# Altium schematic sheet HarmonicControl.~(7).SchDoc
size A
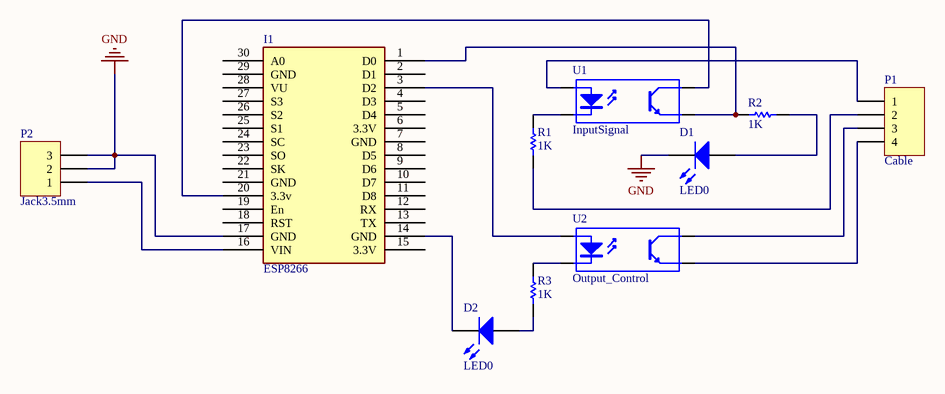
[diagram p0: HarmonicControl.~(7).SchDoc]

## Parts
D1  LED0  [LED-0]
D2  LED0  [LED-0]
I1  ESP8266  [ESP8266_Node_MCU_V3]
P1  Cable  [HDR1X4]
P2  Jack3.5mm  [HDR1X3]
R1  value 1K  [AXIAL-0.3]  (hidden comment: Res1)
R2  value 1K  [AXIAL-0.3]  (hidden comment: Res1)
R3  value 1K  [AXIAL-0.3]  (hidden comment: Res1)
U1  InputSignal  [DIP-4]
U2  Output_Control  [DIP-4]

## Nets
GND: D1.2(K) I1.17(GND) P2.2 P2.3
NetD1_1: D1.1(A) R2.2
NetD2_1: D2.1(A) R3.1
NetD2_2: D2.2(K) I1.14(GND)
NetI1_1: I1.1(D0) R2.1 U1.3(E)
NetI1_3: I1.3(D2) U2.1(A)
NetI1_16: I1.16(VIN) P2.1
NetI1_20: I1.20(3.3v) U1.4(C)
NetP1_1: P1.1 U1.1(A)
NetP1_2: P1.2 R1.1
NetP1_3: P1.3 U2.4(C)
NetP1_4: P1.4 U2.3(E)
NetR1_2: R1.2 U1.2(K)
NetR3_2: R3.2 U2.2(K)

Not connected (* = marked no-connect by the designer): I1 2(D1) 4(D3) 5(D4) 6(3.3V) 7(GND) 8(D5) 9(D6) 10(D7) 11(D8) 12(RX) 13(TX) 15(3.3V) 18(RST) 19(En) 21(GND) 22(SK) 23(SO) 24(SC) 25(S1) 26(S2) 27(S3) 28(VU) 29(GND) 30(A0)

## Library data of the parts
D1 D2 = LED0: Typical INFRARED GaAs LED
I1 = ESP8266_Node_MCU_V3
P1 = Header 4: Header, 4-Pin
P2 = Header 3: Header, 3-Pin
R1-R3 = Res1: Resistor
U1 U2 = Optoisolator1: 4-Pin Phototransistor Optocoupler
